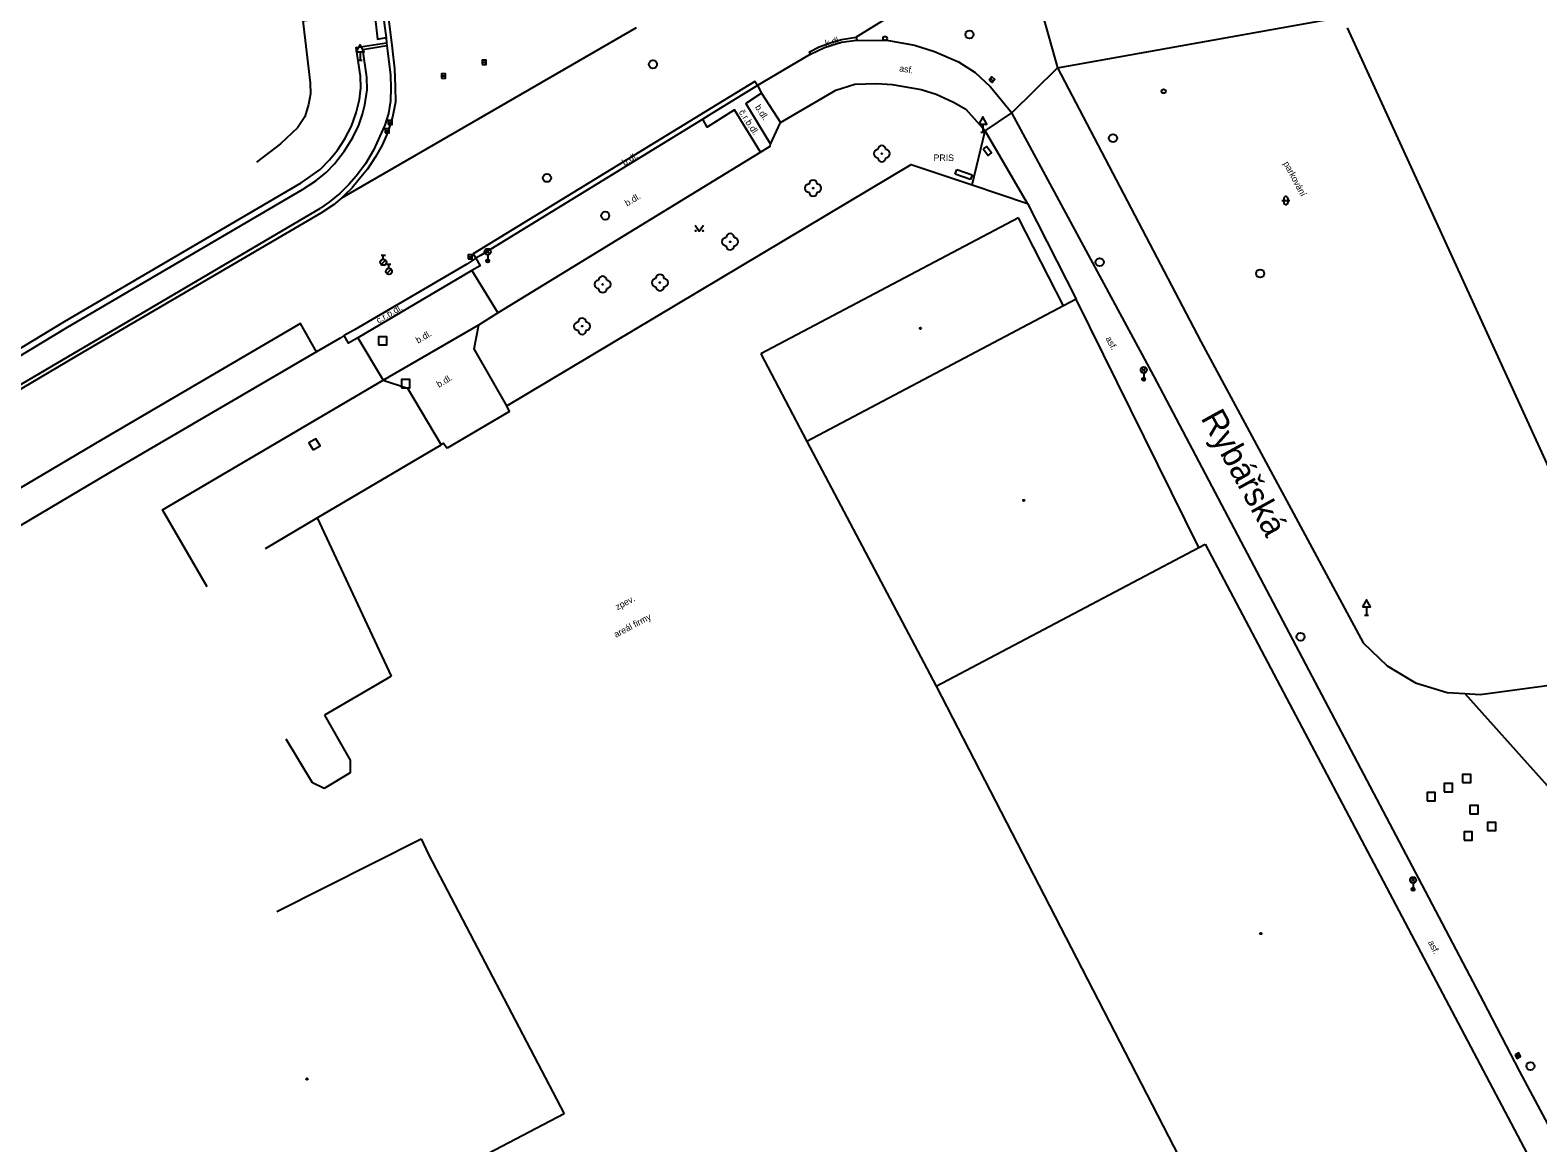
# Model space of a CAD drawing. Extents: x -599770 to -598493, y -1162076 to -1159209.
# Drawn here: x -599554.2 to -599461.6, y -1161446 to -1161377.7 of the extents above; entities that cross this region are included whole.
import ezdxf

# ---------------------------------------------------------------- set-up
doc = ezdxf.new("R2010")
doc.units = 0
doc.layers.add('Podklad', color=7, linetype='Continuous')

msp = doc.modelspace()

# ---------------------------------------------------------------- linework, layer by layer
at = {"layer": 'Podklad'}
for p, q in [((-599534.045, -1161379.5), (-599533.795, -1161379.5)), ((-599533.92, -1161378.991), (-599533.92, -1161379.5)), ((-599526.425, -1161379.63), (-599526.175, -1161379.63)), ((-599528.925, -1161380.47), (-599528.675, -1161380.47)), ((-599495.197, -1161380.621), (-599495.003, -1161380.779)), ((-599532.195, -1161383.32), (-599531.945, -1161383.32)), ((-599495.67, -1161383.421), (-599495.67, -1161383.93)), ((-599532.375, -1161383.84), (-599532.125, -1161383.84)), ((-599495.795, -1161383.93), (-599495.545, -1161383.93)), ((-599477.303, -1161388.118), (-599476.803, -1161388.118)), ((-599477.178, -1161387.993), (-599477.178, -1161388.243)), ((-599476.928, -1161387.993), (-599476.928, -1161388.243)), ((-599532.619, -1161392.046), (-599532.354, -1161391.781)), ((-599532.615, -1161391.472), (-599532.365, -1161391.472)), ((-599532.49, -1161391.722), (-599532.49, -1161391.472)), ((-599527.285, -1161391.58), (-599527.035, -1161391.58)), ((-599526.212, -1161391.4), (-599525.947, -1161391.135)), ((-599526.212, -1161391.135), (-599525.947, -1161391.4)), ((-599526.08, -1161391.455), (-599526.08, -1161391.83)), ((-599532.279, -1161392.606), (-599532.014, -1161392.341)), ((-599532.275, -1161392.032), (-599532.025, -1161392.032)), ((-599532.15, -1161392.282), (-599532.15, -1161392.032)), ((-599485.913, -1161398.66), (-599485.648, -1161398.395)), ((-599485.913, -1161398.395), (-599485.648, -1161398.66)), ((-599485.78, -1161398.715), (-599485.78, -1161399.09)), ((-599472.1, -1161413.071), (-599472.1, -1161413.58)), ((-599472.225, -1161413.58), (-599471.975, -1161413.58)), ((-599469.372, -1161429.99), (-599469.107, -1161429.725)), ((-599469.372, -1161429.725), (-599469.107, -1161429.99)), ((-599469.24, -1161430.045), (-599469.24, -1161430.42)), ((-599462.864, -1161440.527), (-599462.756, -1161440.753))]:
    msp.add_line(p, q, dxfattribs=at)
for points in [[(-599488.19, -1161368.65), (-599503.44, -1161378.09)], [(-599532.87, -1161373.47), (-599532.6, -1161373.43), (-599531.94, -1161378.76), (-599531.81, -1161380.04), (-599531.76, -1161381.14), (-599531.75, -1161382.08), (-599531.93, -1161382.99), (-599532.21, -1161383.91), (-599532.57, -1161384.71), (-599532.97, -1161385.44), (-599533.47, -1161386.19), (-599533.97, -1161386.81), (-599534.41, -1161387.33), (-599534.89, -1161387.82), (-599535.037, -1161387.943), (-599535.56, -1161388.38), (-599536.32, -1161388.89), (-599550.93, -1161397.43), (-599565.6, -1161406.12), (-599565.76, -1161405.87)], [(-599532.83, -1161373.74), (-599532.76, -1161374.46), (-599532.42, -1161377.39), (-599532.32, -1161378.1)], [(-599537.44, -1161377.08), (-599533.06, -1161376.38), (-599532.84, -1161378.21), (-599532.32, -1161378.1)], [(-599537.44, -1161377.08), (-599536.99, -1161380.88)], [(-599493.89, -1161382.74), (-599491.08, -1161379.97), (-599471.16, -1161376.4)], [(-599491.97, -1161376.83), (-599491.08, -1161379.97), (-599482.27, -1161396.78), (-599472.31, -1161415.29)], [(-599535.037, -1161387.943), (-599516.93, -1161377.49)], [(-599458, -1161410.87), (-599473.27, -1161377.51)], [(-599566.71, -1161404.41), (-599552.08, -1161395.55), (-599537.54, -1161387.04), (-599536.36, -1161386.22), (-599535.79, -1161385.62), (-599535.31, -1161385.02), (-599534.85, -1161384.32), (-599534.45, -1161383.55), (-599534.15, -1161382.74), (-599533.96, -1161381.91), (-599533.88, -1161381.19), (-599533.9, -1161380.49), (-599534.15, -1161378.71), (-599532.29, -1161378.43)], [(-599566.49, -1161404.72), (-599551.88, -1161395.89), (-599537.45, -1161387.44), (-599536.63, -1161386.9), (-599536.01, -1161386.39), (-599535.49, -1161385.87), (-599534.87, -1161385.07), (-599534.36, -1161384.24), (-599534, -1161383.5), (-599533.76, -1161382.81), (-599533.62, -1161382.24), (-599533.49, -1161381.32), (-599533.5, -1161380.54), (-599533.74, -1161378.85), (-599532.27, -1161378.6)], [(-599532.27, -1161378.6), (-599532.04, -1161380.41), (-599532.02, -1161381.19), (-599532.04, -1161381.99), (-599532.18, -1161382.77), (-599532.39, -1161383.5), (-599533.1, -1161385.03), (-599533.58, -1161385.86), (-599534.16, -1161386.63), (-599534.61, -1161387.14), (-599535.14, -1161387.67), (-599535.8, -1161388.2), (-599536.34, -1161388.58)], [(-599532.32, -1161378.1), (-599532.29, -1161378.43)], [(-599532.29, -1161378.43), (-599532.27, -1161378.6)], [(-599506.25, -1161379.12), (-599506.32, -1161378.98), (-599505.71, -1161378.67), (-599504.99, -1161378.41), (-599504.34, -1161378.23), (-599503.44, -1161378.09), (-599503.4, -1161378.26)], [(-599506.25, -1161379.12), (-599505.4, -1161378.72), (-599504.34, -1161378.4), (-599503.4, -1161378.26)], [(-599503.4, -1161378.26), (-599501.47, -1161378.28), (-599499.86, -1161378.57), (-599498.64, -1161378.96), (-599497.17, -1161379.61), (-599496.14, -1161380.25), (-599495.19, -1161381.13), (-599493.89, -1161382.74)], [(-599506.25, -1161379.12), (-599509.2, -1161380.87), (-599509.51, -1161381.05)], [(-599536.99, -1161380.88), (-599536.97, -1161381.56), (-599537.08, -1161382.23), (-599537.32, -1161382.97), (-599537.76, -1161383.66), (-599538.81, -1161384.64), (-599540.28, -1161385.76)], [(-599509.51, -1161381.05), (-599509.68, -1161380.81), (-599512.35, -1161382.45), (-599526.97, -1161391.4), (-599526.81, -1161391.65)], [(-599509.51, -1161381.05), (-599512.32, -1161382.78), (-599512.87, -1161383.12)], [(-599509.26, -1161381.53), (-599510.23, -1161382.16), (-599508.7, -1161384.65)], [(-599509.51, -1161381.05), (-599509.26, -1161381.53)], [(-599509.26, -1161381.53), (-599508.1, -1161383.33)], [(-599508.1, -1161383.33), (-599504.7, -1161381.34)], [(-599504.7, -1161381.34), (-599503.52, -1161380.97), (-599502.18, -1161380.94), (-599501.23, -1161381), (-599499.45, -1161381.29), (-599498.54, -1161381.59), (-599497.47, -1161382.08), (-599496.72, -1161382.51), (-599495.52, -1161383.83)], [(-599509.32, -1161385.14), (-599510.92, -1161382.55), (-599512.6, -1161383.61), (-599512.87, -1161383.12)], [(-599512.87, -1161383.12), (-599526.52, -1161391.49), (-599526.81, -1161391.65)], [(-599508.7, -1161384.65), (-599508.1, -1161383.33)], [(-599496.33, -1161387.16), (-599495.52, -1161383.83), (-599493.89, -1161382.74)], [(-599422.74, -1161519.45), (-599423.87, -1161515.62), (-599428.72, -1161506.24), (-599442.85, -1161479.31), (-599457.16, -1161451.95), (-599462.69, -1161441.61), (-599464.91, -1161437.31), (-599468.69, -1161430.14), (-599485.16, -1161398.89), (-599493.89, -1161382.74)], [(-599492.93, -1161388.3), (-599495.52, -1161383.83)], [(-599525.45, -1161395.02), (-599509.32, -1161385.14)], [(-599509.32, -1161385.14), (-599508.73, -1161384.78), (-599508.7, -1161384.65)], [(-599524.9, -1161400.72), (-599500.07, -1161385.91), (-599496.33, -1161387.16), (-599492.93, -1161388.3)], [(-599497.36, -1161386.5), (-599497.26, -1161386.22)], [(-599497.26, -1161386.22), (-599496.33, -1161386.54)], [(-599496.43, -1161386.82), (-599497.36, -1161386.5)], [(-599496.33, -1161386.54), (-599496.43, -1161386.82)], [(-599565.76, -1161405.87), (-599536.34, -1161388.58)], [(-599492.93, -1161388.3), (-599489.93, -1161394.18)], [(-599513.33, -1161389.635), (-599513.08, -1161390.01), (-599512.83, -1161389.635)], [(-599493.47, -1161389.18), (-599509.31, -1161397.53)], [(-599490.71, -1161394.59), (-599493.47, -1161389.18)], [(-599526.81, -1161391.65), (-599527.37, -1161392.02), (-599534.27, -1161396.06), (-599534.89, -1161396.4)], [(-599526.81, -1161391.65), (-599526.55, -1161392.12), (-599527.06, -1161392.41)], [(-599527.06, -1161392.41), (-599534.06, -1161396.55)], [(-599527.06, -1161392.41), (-599525.45, -1161395.02)], [(-599490.71, -1161394.59), (-599506.47, -1161402.91)], [(-599489.93, -1161394.18), (-599490.71, -1161394.59)], [(-599482.4, -1161409.43), (-599489.93, -1161394.18)], [(-599524.9, -1161400.72), (-599526.92, -1161397.22), (-599526.63, -1161395.75), (-599525.45, -1161395.02)], [(-599536.59, -1161397.41), (-599537.58, -1161395.67), (-599549.83, -1161402.83), (-599563.53, -1161410.94)], [(-599534.89, -1161396.4), (-599535.14, -1161396.58), (-599536.59, -1161397.41)], [(-599534.06, -1161396.55), (-599534.62, -1161396.88), (-599534.89, -1161396.4)], [(-599532.49, -1161399.16), (-599526.63, -1161395.75)], [(-599536.59, -1161397.41), (-599548.79, -1161404.53), (-599562.55, -1161412.68), (-599573.32, -1161419.39), (-599573.61, -1161419.56)], [(-599534.06, -1161396.55), (-599532.49, -1161399.16)], [(-599509.31, -1161397.53), (-599506.47, -1161402.91)], [(-599543.32, -1161411.85), (-599546.05, -1161407.12), (-599532.49, -1161399.16)], [(-599532.49, -1161399.16), (-599531.01, -1161399.64), (-599528.94, -1161403.13)], [(-599524.73, -1161401.07), (-599528.57, -1161403.32)], [(-599524.73, -1161401.07), (-599524.9, -1161400.72)], [(-599528.94, -1161403.13), (-599528.8, -1161403.02), (-599528.57, -1161403.32)], [(-599506.47, -1161402.91), (-599498.54, -1161417.94)], [(-599536.55, -1161407.6), (-599528.94, -1161403.13)], [(-599539.73, -1161409.49), (-599536.55, -1161407.6)], [(-599536.55, -1161407.6), (-599532, -1161417.34)], [(-599498.54, -1161417.94), (-599482.4, -1161409.43)], [(-599482.4, -1161409.43), (-599482, -1161409.22)], [(-599482, -1161409.22), (-599461.86, -1161447.37)], [(-599472.31, -1161415.29), (-599470.84, -1161416.7), (-599469.09, -1161417.73), (-599467.14, -1161418.33), (-599466.07, -1161418.39), (-599465.11, -1161418.45)], [(-599532.28, -1161417.5), (-599536.11, -1161419.73)], [(-599532, -1161417.34), (-599532.28, -1161417.5)], [(-599465.11, -1161418.45), (-599455.08, -1161417.11)], [(-599498.54, -1161417.94), (-599478.95, -1161455.88)], [(-599466.07, -1161418.39), (-599458.21, -1161427.15)], [(-599536.11, -1161419.73), (-599534.52, -1161422.48)], [(-599536.85, -1161423.89), (-599538.46, -1161421.2)], [(-599534.52, -1161423.27), (-599536.13, -1161424.23)], [(-599534.52, -1161422.48), (-599534.52, -1161423.27)], [(-599536.13, -1161424.23), (-599536.85, -1161423.89)], [(-599539.04, -1161431.79), (-599530.16, -1161427.32)], [(-599530.16, -1161427.32), (-599529.72, -1161428.29)], [(-599529.72, -1161428.29), (-599521.38, -1161444.22)], [(-599521.38, -1161444.22), (-599535.44, -1161451.58)]]:
    msp.add_lwpolyline(points, dxfattribs=at)
for points in [[(-599534.17, -1161378.991), (-599533.67, -1161378.991), (-599533.92, -1161378.558)], [(-599526.425, -1161379.755), (-599526.175, -1161379.755), (-599526.175, -1161379.505), (-599526.425, -1161379.505)], [(-599528.925, -1161380.595), (-599528.675, -1161380.595), (-599528.675, -1161380.345), (-599528.925, -1161380.345)], [(-599495.276, -1161380.717), (-599495.083, -1161380.876), (-599494.924, -1161380.683), (-599495.117, -1161380.524)], [(-599532.195, -1161383.445), (-599531.945, -1161383.445), (-599531.945, -1161383.195), (-599532.195, -1161383.195)], [(-599495.92, -1161383.421), (-599495.42, -1161383.421), (-599495.67, -1161382.988)], [(-599532.375, -1161383.965), (-599532.125, -1161383.965), (-599532.125, -1161383.715), (-599532.375, -1161383.715)], [(-599495.643, -1161384.951), (-599495.333, -1161385.344), (-599495.137, -1161385.189), (-599495.447, -1161384.796)], [(-599527.285, -1161391.705), (-599527.035, -1161391.705), (-599527.035, -1161391.455), (-599527.285, -1161391.455)], [(-599532.78, -1161396.98), (-599532.28, -1161396.98), (-599532.28, -1161396.48), (-599532.78, -1161396.48)], [(-599531.37, -1161399.62), (-599530.87, -1161399.62), (-599530.87, -1161399.12), (-599531.37, -1161399.12)], [(-599536.808, -1161403.432), (-599536.377, -1161403.178), (-599536.632, -1161402.748), (-599537.062, -1161403.002)], [(-599472.35, -1161413.071), (-599471.85, -1161413.071), (-599472.1, -1161412.638)], [(-599466.2, -1161423.87), (-599465.7, -1161423.87), (-599465.7, -1161423.37), (-599466.2, -1161423.37)], [(-599467.32, -1161424.43), (-599466.82, -1161424.43), (-599466.82, -1161423.93), (-599467.32, -1161423.93)], [(-599468.38, -1161424.98), (-599467.88, -1161424.98), (-599467.88, -1161424.48), (-599468.38, -1161424.48)], [(-599465.75, -1161425.78), (-599465.25, -1161425.78), (-599465.25, -1161425.28), (-599465.75, -1161425.28)], [(-599466.11, -1161427.4), (-599465.61, -1161427.4), (-599465.61, -1161426.9), (-599466.11, -1161426.9)], [(-599464.66, -1161426.81), (-599464.16, -1161426.81), (-599464.16, -1161426.31), (-599464.66, -1161426.31)], [(-599462.977, -1161440.582), (-599462.868, -1161440.807), (-599462.643, -1161440.698), (-599462.752, -1161440.473)]]:
    msp.add_lwpolyline(points, close=True, dxfattribs=at)
for centre, radius in [((-599496.49, -1161377.92), 0.25), ((-599501.67, -1161378.16), 0.125), ((-599515.93, -1161379.75), 0.25), ((-599484.56, -1161381.41), 0.125), ((-599487.67, -1161384.29), 0.25), ((-599501.87, -1161385.24), 0.025), ((-599522.44, -1161386.73), 0.25), ((-599506.09, -1161387.36), 0.025), ((-599518.86, -1161389.05), 0.25), ((-599513.305, -1161389.985), 0.025), ((-599512.855, -1161389.985), 0.025), ((-599511.19, -1161390.65), 0.025), ((-599532.49, -1161391.91), 0.188), ((-599526.08, -1161391.267), 0.188), ((-599526.08, -1161391.83), 0.1), ((-599526.08, -1161391.83), 0.0723), ((-599526.08, -1161391.83), 0.0438), ((-599488.49, -1161391.9), 0.25), ((-599532.15, -1161392.47), 0.188), ((-599478.63, -1161392.6), 0.25), ((-599519.02, -1161393.27), 0.025), ((-599515.5, -1161393.16), 0.025), ((-599520.28, -1161395.84), 0.025), ((-599499.5, -1161395.97), 0.045), ((-599499.5, -1161395.97), 0.0199), ((-599485.78, -1161398.527), 0.188), ((-599485.78, -1161399.09), 0.1), ((-599485.78, -1161399.09), 0.0723), ((-599485.78, -1161399.09), 0.0438), ((-599493.15, -1161406.54), 0.045), ((-599493.15, -1161406.54), 0.0199), ((-599476.15, -1161414.91), 0.25), ((-599469.24, -1161429.858), 0.188), ((-599469.24, -1161430.42), 0.1), ((-599469.24, -1161430.42), 0.0723), ((-599469.24, -1161430.42), 0.0438), ((-599478.59, -1161433.14), 0.045), ((-599478.59, -1161433.14), 0.0199), ((-599462.03, -1161441.28), 0.25), ((-599537.18, -1161442.07), 0.045), ((-599537.18, -1161442.07), 0.0199)]:
    msp.add_circle(centre, radius, dxfattribs=at)
for centre, radius, start, end in [((-599502.12, -1161385.24), 0.25, 90, 270), ((-599501.87, -1161384.99), 0.25, 0, 180), ((-599501.62, -1161385.24), 0.25, 270, 90), ((-599501.87, -1161385.49), 0.25, 180, 0), ((-599506.34, -1161387.36), 0.25, 90, 270), ((-599506.09, -1161387.11), 0.25, 0, 180), ((-599505.84, -1161387.36), 0.25, 270, 90), ((-599506.09, -1161387.61), 0.25, 180, 0), ((-599477.053, -1161387.993), 0.125, 0, 180), ((-599477.053, -1161388.243), 0.125, 180, 0), ((-599511.44, -1161390.65), 0.25, 90, 270), ((-599511.19, -1161390.4), 0.25, 0, 180), ((-599511.19, -1161390.9), 0.25, 180, 0), ((-599510.94, -1161390.65), 0.25, 270, 90), ((-599519.02, -1161393.02), 0.25, 0, 180), ((-599515.5, -1161392.91), 0.25, 0, 180), ((-599519.27, -1161393.27), 0.25, 90, 270), ((-599519.02, -1161393.52), 0.25, 180, 0), ((-599518.77, -1161393.27), 0.25, 270, 90), ((-599515.75, -1161393.16), 0.25, 90, 270), ((-599515.5, -1161393.41), 0.25, 180, 0), ((-599515.25, -1161393.16), 0.25, 270, 90), ((-599520.53, -1161395.84), 0.25, 90, 270), ((-599520.28, -1161395.59), 0.25, 0, 180), ((-599520.03, -1161395.84), 0.25, 270, 90), ((-599520.28, -1161396.09), 0.25, 180, 0)]:
    msp.add_arc(centre, radius, start, end, dxfattribs=at)

# ---------------------------------------------------------------- texts
for s, height, rotation, p in [('k.dl.', 0.4, 14.33, (-599505.3, -1161378.66)), ('asf.', 0.4, 351, (-599500.82, -1161380.18)), ('č.r.b.dl.', 0.4, 303, (-599510.67, -1161382.69)), ('b.dl.', 0.4, 303, (-599509.68, -1161382.39)), ('b.dl.', 0.4, 31.23, (-599517.68, -1161386)), ('parkování', 0.4, 298, (-599477.22, -1161385.84)), ('b.dl.', 0.4, 31, (-599517.51, -1161388.49)), ('č.r.b.dl.', 0.4, 30, (-599532.79, -1161395.68)), ('b.dl.', 0.4, 30, (-599530.36, -1161396.91)), ('asf.', 0.4, 298, (-599488.14, -1161396.59)), ('b.dl.', 0.4, 30, (-599529.08, -1161399.62)), ('Rybářská', 1.5, 298.77, (-599482.31, -1161401.47)), ('zpev.', 0.4, 28, (-599518.11, -1161413.29)), ('areál firmy', 0.4, 28, (-599518.2, -1161414.98)), ('asf.', 0.4, 297.83, (-599468.34, -1161433.68))]:
    msp.add_text(s, height=height, rotation=rotation, dxfattribs=at).set_placement(p)
msp.add_text('PRIS', height=0.4, dxfattribs=at).set_placement((-599498.69, -1161385.69))

doc.saveas('drawing.dxf')
